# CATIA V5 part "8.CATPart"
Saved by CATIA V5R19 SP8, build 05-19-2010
Part number: 8
Bounding box of the stored display mesh (mm): x -289.853 to 157.737, y 80.761 to 583.056, z -200.397 to 53.976
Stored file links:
  G:\EU_thinkMotion\CFAO_2010\MMS_groupe3\MMS_groupe3\A reprendre\bblot\BLOT\8.CATPart
  J:\CFAO_IFMA\Amortisseur.CATProduct
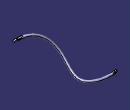
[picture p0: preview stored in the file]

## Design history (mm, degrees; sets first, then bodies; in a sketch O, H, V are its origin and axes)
External parameters (linked from other documents)
  `External.Diamètre bielle` = 20 mm
Set1
  Sketch1, origin (61.2358, -4.8586, -0.7236), H (-0.4492, -0.8928, 0.0346), V (0.3521, -0.1413, 0.9252), geometry linked from another document
  DatumCurve1: linked copy from another document
  Point1 "C": linked copy from another document
  Plane1: linked copy from another document
  Point2 "D": linked copy from another document
Set2
  Plane2: type OffsetPt, RefPlane xy-plane, RefPoint Point1
  Plane3: type Tangent, Support face of Rib1, RefPoint Point2
  Plane4: type OffsetPt, RefPlane xy-plane, RefPoint Point2
  Line1: stored without definition
  DatumCurve2
  Point3 "D": stored without definition
Body1 (main body)
  Rib1: profile Sketch1, centre curve DatumCurve1
  SolidCombine1: FirstComponentProfile Sketch8, FirstComponentDirection Sketch8, SecondComponentProfile Sketch9, SecondComponentDirection Sketch9
  Sketch2 on face of Rib1, origin (60.934, -4.259, -2.0583), H (0.4532, 0.8911, -0.0239), V (0.3469, -0.1516, 0.9256)
    arc A1 centre (123.4386, 37.8242) radius 15 from (137.5808, 42.8242) to (109.2965, 42.8242) ccw
    point P1 (123.4386, 37.8242)
    line L1 (109.2965, 42.8242) -> (137.5808, 42.8242)
    point P3 (137.5808, 42.8242)
    reference projected line E1 (308.2779, 42.8242) -> (325.5984, 42.8242) from edge [face of SolidCombine1 from Sketch9.A1 | face of SolidCombine1 from Sketch8.L1]
    line L2 (137.5808, 32.8242) -> (109.2965, 32.8242)
    point P4 (137.5808, 32.8242)
    arc A2 centre (123.4386, 37.8242) radius 15 from (109.2965, 32.8242) to (137.5808, 32.8242) ccw
    reference projected point E2 (123.4386, 37.8242) from Point1
    axis line L3 (137.5808, 32.8242) -> (137.5808, 42.8242)
    point P6 (137.5808, 42.8242)
    point P7 (137.5808, 32.8242)
    radius A1 = 15 {= `External.Diamètre bielle` /2+5mm}
    horizontal: L1 H, L2 H
    coincidence: L1 E1, A1 A2, P1 E2, P6 A1, L3 P3, P7 P4
    vertical: L3 V
  Pocket1: profile Sketch2, direction (-0.8211, 0.4278, 0.3778), length 40
  Sketch3 on face of SolidCombine1 from Sketch8.L1, origin (154.2235, 294.1836, 58.1302), H (0.9375, 0.0275, -0.3469), V (0.0271, 0.9881, 0.1517)
    point P1 (-18.2958, -196.7883)
    reference projected point E1 (-18.2958, -196.7883) from Point1
    coincidence: P1 E1
  Hole1: placed by Sketch3, at (131.7344, 99.242, 34.6279) direction (0, 0, -1), diameter 10, through (limit type 3)
  SolidCombine2: FirstComponentProfile Sketch6, FirstComponentDirection Sketch6, SecondComponentProfile Sketch7, SecondComponentDirection Sketch7
  Sketch4 on Plane3, origin (-169.8914, -30.7114, 8.099), H (-0.1659, 0.9861, 0.0095), V (-0.0029, -0.0101, 0.9999)
    line L1 (612.0879, -218.0132) -> (612.0879, -189.7289)
    line L2 (602.0879, -189.7289) -> (602.0879, -218.0132)
    point P3 (602.0879, -189.7289)
    axis line L3 (602.0879, -189.7289) -> (612.0879, -189.7289)
    arc A1 centre (607.0879, -203.871) radius 15 from (612.0879, -218.0132) to (612.0879, -189.7289) ccw
    reference projected circle E1 centre (607.0879, -203.871) radius 10 from edge [face of Rib1 | face of Rib1]
    reference projected circle E2 centre (607.0879, -203.871) radius 10 from edge [face of Rib1 | face of Rib1]
    arc A2 centre (607.0879, -203.871) radius 15 from (602.0879, -189.7289) to (602.0879, -218.0132) ccw
    reference projected line E3 (612.0879, -212.5313) -> (612.0879, -195.2108) from edge [face of SolidCombine2 from Sketch7.A1 | face of SolidCombine2 from Sketch6.L1]
    reference projected line E4 (602.0879, -195.2108) -> (602.0879, -212.5313) from edge [face of SolidCombine2 from Sketch7.A1 | face of SolidCombine2 from Sketch6.L2]
    distance A1 E2 = 5
    concentricity: A1 E1
    coincidence: P3 A1, A1 A2, L1 E3, E4 L2
  Pocket2: profile Sketch4, direction (0.9861, 0.1658, 0.0046), length 20
  Pocket3: profile Sketch4, direction (0.9861, 0.1658, 0.0046), length 20
  Sketch5 on face of Pocket3, origin (-284.5073, 572.6086, -187.7765), H (0.9861, 0.1659, 0.0016), V (0, 0.0096, -1)
    point P1 (13.8701, 2.1983)
    reference projected point E1 (13.8701, 2.1983) from Point3
    coincidence: P1 E1
  Hole2: placed by Sketch5, at (-270.8294, 574.9305, -189.9526) direction (0.1659, -0.9861, -0.0095), diameter 10, through (limit type 3)
  Sketch6 on face of Rib1, origin (-169.8914, -30.7114, 8.099), H (0.1659, -0.9861, -0.0095), V (-0.0029, -0.0101, 0.9999)
    line L1 (-612.0879, -195.2108) -> (-612.0879, -212.5313)
    point P2 (-612.0879, -212.5313)
    line L2 (-602.0879, -195.2108) -> (-602.0879, -212.5313)
    axis line L3 (-602.0879, -195.2108) -> (-612.0879, -195.2108)
    arc A1 centre (-607.0879, -203.871) radius 10 from (-602.0879, -195.2108) to (-612.0879, -195.2108) ccw
    reference projected circle E1 centre (-607.0879, -203.871) radius 10 from edge [face of Rib1 | face of Rib1]
    reference projected circle E2 centre (-607.0879, -203.871) radius 10 from edge [face of Rib1 | face of Rib1]
    arc A2 centre (-607.0879, -203.871) radius 10 from (-612.0879, -212.5313) to (-602.0879, -212.5313) ccw
    distance L1 L2 = 10
    concentricity: A1 E1
    coincidence: A1 E2, P2 A1, A1 A2
    perpendicularity: L3 L1
    horizontal: L3 H
  Sketch7 on Plane4, origin (0, 0, -190), H (1, 0, 0), V (0, 1, 0)
    line L1 (-271.6585, 579.8615) -> (-281.52, 578.203)
    line L2 (-268.3415, 560.1385) -> (-278.203, 558.48)
    arc A1 centre (-279.8615, 568.3415) radius 10 from (-278.203, 558.48) to (-281.52, 578.203) cw
    line L3 (-271.6585, 579.8615) -> (-268.3415, 560.1385)
    reference intersected line E1 through (-169.3876, -28.244) direction (-0.1659, 0.9862) from Plane3
    reference projected point E2 (-270, 570) from Point2
    distance L2 L1 = 20 {= `External.Diamètre bielle`}
    length L1 = 10
    tangency: A1 L1, L2 A1
    perpendicularity: L3 L1
    coincidence: L3 E1
    midpoint: E2 L3
  Sketch8 on face of Rib1, origin (60.934, -4.259, -2.0583), H (0.4532, 0.8911, -0.0239), V (0.3469, -0.1516, 0.9256)
    arc A1 centre (123.4386, 37.8242) radius 10 from (114.7784, 42.8242) to (114.7784, 32.8242) ccw
    point P1 (123.4386, 37.8242)
    reference projected point E1 (123.4386, 37.8242) from Point1
    reference projected circle E2 centre (123.4386, 37.8242) radius 10 from Sketch1
    point P3 (132.0989, 32.8242)
    arc A2 centre (123.4386, 37.8242) radius 10 from (132.0989, 32.8242) to (132.0989, 42.8242) ccw
    line L1 (132.0989, 42.8242) -> (114.7784, 42.8242)
    line L2 (132.0989, 32.8242) -> (114.7784, 32.8242)
    point P6 (132.0989, 32.8242)
    axis line L3 (132.0989, 42.8242) -> (132.0989, 32.8242)
    point P7 (132.0989, 32.8242)
    distance L1 L2 = 10
    coincidence: P1 E1, A1 E2, A1 A2, P3 P6, P7 L2, P7 A1
    horizontal: L1 H, L2 H
    vertical: L3 V
  Sketch9 on Plane2, origin (0, 0, 30), H (1, 0, 0), V (0, 1, 0)
    line L1 (125.3797, 91.1313) -> (143.117, 81.8908)
    point P2 (143.117, 81.8908)
    line L2 (125.3797, 91.1313) -> (134.6203, 108.8687)
    line L3 (134.6203, 108.8687) -> (152.3576, 99.6281)
    point P4 (152.3576, 99.6281)
    arc A1 centre (147.7373, 90.7595) radius 10 from (143.117, 81.8908) to (152.3576, 99.6281) ccw
    point P5 (147.7373, 90.7595)
    point P6 (143.117, 81.8908)
    point P7 (152.3576, 99.6281)
    reference projected point E1 (130, 100) from Point1
    reference intersected line E2 through (72.9681, -9.4734) direction (-0.462, -0.8869) from Plane1
    length L2 = 20 {= `External.Diamètre bielle`}
    distance P5 L2 = 20
    parallelism: L3 L1
    tangency: A1 L3, A1 L1
    coincidence: P6 P2, E2 L2, P7 P4
    midpoint: L2 E1
    perpendicularity: L2 L3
